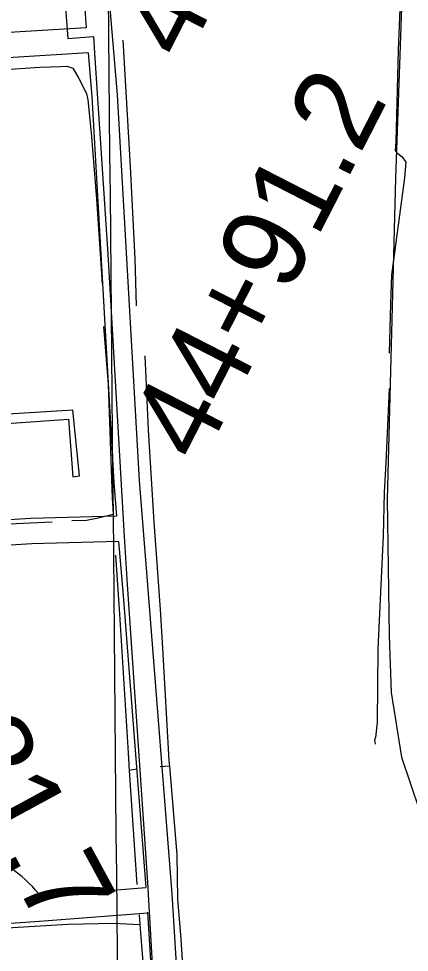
# Model space of a CAD drawing. Extents: x 3598634 to 3636690, y 517270 to 542944.
# Drawn here: x 3618480 to 3618943, y 532624 to 533730 of the extents above; entities that cross this region are included whole.
import ezdxf

# ---------------------------------------------------------------- set-up
doc = ezdxf.new("R2010")
doc.units = 0
for name, color, linetype in [('V-GRID-MAJR', 7, 'Continuous'), ('V-ROAD-CNTR', 7, 'Continuous'), ('V-SITE-OTLN', 7, 'Continuous'), ('V-SURV-IDEN', 7, 'Continuous'), ('V-TOPO-SHOR', 7, 'Continuous'), ('V-UTIL-LINE', 7, 'Continuous')]:
    doc.layers.add(name, color=color, linetype=linetype)

msp = doc.modelspace()

# ---------------------------------------------------------------- linework, layer by layer
at = {"layer": 'V-GRID-MAJR'}
msp.add_spline([(3618688.126, 522824.368), (3618631.739, 528881.623), (3618575.3200000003, 534942.3470000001), (3618518.901, 541003.085), (3618518.869, 541006.5380000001)], degree=3, dxfattribs=at)
at = {"layer": 'V-ROAD-CNTR'}
for points in [[(3619219.9145215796, 534324.0093257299), (3619206.102549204, 534275.35442304), (3619176.9376075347, 534236.3695010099), (3619115.1567310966, 534156.29966115), (3619042.2828768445, 534040.5618926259), (3619000.4559604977, 533979.1660154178), (3618969.343022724, 533912.5291486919), (3618942.837075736, 533846.1042815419), (3618935.526090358, 533799.4893747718), (3618926.589108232, 533541.027891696), (3618916.4771284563, 533160.012653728), (3618919.048123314, 532999.0249757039), (3618921.288118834, 532931.6421104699), (3618933.62509416, 532854.8872639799), (3618954.7500519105, 532791.593390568), (3618968.012025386, 532734.3305050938), (3618985.6189901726, 532604.676764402), (3619018.862923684, 532130.184713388), (3619043.9958734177, 531655.553662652), (3618810.58034025, 531632.7107083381), (3618782.5033964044, 531631.8167101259), (3618729.4055026, 531624.7497242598)], [(3618522.2249169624, 534279.1574154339), (3618527.482906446, 534211.0755515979), (3618558.558844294, 533735.331503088), (3618559.9198415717, 533719.114535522)], [(3618552.134857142, 534281.4674108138), (3618557.4068465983, 534213.207547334), (3618588.4767844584, 533737.5634986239), (3618596.699768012, 533639.6066945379), (3618622.53571634, 533182.582608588), (3618633.446694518, 533048.905875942), (3618661.3826386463, 532693.043587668), (3618688.0935852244, 532257.341459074), (3618714.078533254, 531845.438282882), (3618725.868509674, 531684.253605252), (3618729.4055026, 531624.7497242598)], [(3618559.92084157, 533719.114535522), (3618312.0443373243, 533703.7455662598), (3618179.040603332, 533693.0975875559), (3618051.9228575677, 533682.7066083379), (3617937.045087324, 533677.777618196), (3617826.615308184, 533673.2776271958)], [(3618562.429836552, 533689.212595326), (3618314.170333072, 533673.819626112), (3618274.4384125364, 533670.638632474)], [(3618562.429836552, 533689.212595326), (3618566.7698278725, 533637.504698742), (3618592.6037762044, 533180.5146127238), (3618595.884769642, 533140.323693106)], [(3618595.88576964, 533140.3226931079), (3618494.1659730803, 533137.730698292), (3618310.5403403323, 533126.1567214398)], [(3618598.3297647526, 533110.3757530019), (3618495.4919704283, 533107.7547582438), (3618216.7555279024, 533090.1857933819), (3617956.3310487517, 533072.857828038), (3617866.8522277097, 533067.4688388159)], [(3618598.3297647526, 533110.3757530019), (3618603.542754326, 533046.5118807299), (3618630.7026227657, 532700.5320160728)], [(3618505.311465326, 532690.7503942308), (3618503.6532838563, 532692.9208551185), (3618499.962415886, 532697.3708852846), (3618496.097971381, 532701.6652087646), (3618492.0672013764, 532705.7986735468), (3618487.876376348, 532709.7649900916), (3618483.530859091, 532713.5565683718), (3618479.042725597, 532717.1671712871), (3618474.413681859, 532720.5945192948), (3618469.648790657, 532723.8299944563), (3618464.7632414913, 532726.8678038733), (3618459.758905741, 532729.7016921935), (3618455.1065853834, 532732.0935861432), (3618403.7617469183, 532760.2884909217)], [(3618504.912696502, 532690.7233632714), (3618517.7836619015, 532691.5958350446), (3618630.597150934, 532700.5447059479)], [(3617899.9676740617, 532619.0491477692), (3617937.988811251, 532621.8086414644), (3618108.2972284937, 532634.260796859), (3618324.74355688, 532648.441197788), (3618499.0534782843, 532660.2573448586), (3618519.9843380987, 532661.6761649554), (3618632.969433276, 532670.638648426)], [(3618632.6635868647, 532671.2325881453), (3618658.151645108, 532255.4794627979), (3618684.146593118, 531843.400286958), (3618695.934569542, 531682.2696092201), (3618699.762561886, 531617.8667380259)]]:
    msp.add_lwpolyline(points, dxfattribs=at)
at = {"layer": 'V-SITE-OTLN'}
for points in [[(3616721.157, 533632.576), (3616899.8000000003, 533698.205), (3616988.87, 533732.75), (3616986.457, 533784.804), (3616974.0470000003, 533889.904), (3617157.898, 533936.707), (3617509.6210000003, 534027.0210000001), (3617753.552, 534092.697), (3617870.505, 534121.672), (3617874.2, 534100.176), (3618103.256, 534130.888), (3618391.041, 534154.427), (3618505.486, 534161.542), (3618526.472, 533864.2710000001), (3618538.198, 533706.292), (3618568.566, 533708.84), (3618569.869, 533688.905)], [(3618569.869, 533688.905), (3618585.413, 533450.954), (3618605.043, 533116.261), (3618608.375, 533059.431), (3618632.648, 532706.325), (3618633.8170000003, 532685.753), (3618649.886, 532403.064), (3618673.0160000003, 532133.854), (3618695.2120000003, 531790.738), (3618697.414, 531756.6900000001), (3618708.594, 531603.602), (3618727.133, 531349.7), (3618745.423, 530987.283), (3618752.7800000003, 530856.316)]]:
    msp.add_lwpolyline(points, dxfattribs=at)
at = {"layer": 'V-TOPO-SHOR'}
for p, q in [((3618658.522, 532844.395), (3618647.474, 532843.595)), ((3618620.501, 532840.867), (3618610.923, 532839.316))]:
    msp.add_line(p, q, dxfattribs=at)
for points in [[(3618933.921, 533799.921), (3618929.661, 533692.4130000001), (3618926.686, 533584.178), (3618926.137, 533573.633), (3618927.978, 533570.893), (3618934.329, 533565.937), (3618938.636, 533559.764), (3618937.018, 533541.3420000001), (3618921.799, 533426.474), (3618920.681, 533392.164), (3618918.952, 533333.431)], [(3618603.149, 533704.373), (3618611.892, 533554.554), (3618617.45, 533445.213), (3618619.1890000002, 533389.608)], [(3618418.693, 533665.045), (3618451.924, 533668.607), (3618504.998, 533672.459), (3618529.488, 533673.172), (3618537.432, 533673.42), (3618543.92, 533671.099), (3618551.215, 533658.824), (3618560.2120000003, 533641.174), (3618561.8140000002, 533633.8200000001), (3618565.7260000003, 533594.623), (3618572.234, 533516.297), (3618578.896, 533415.493)], [(3618580.25, 533365.194), (3618585.952, 533296.823), (3618590.8340000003, 533161.743), (3618592.075, 533142.76), (3618592.309, 533139.1950000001)], [(3618629.326, 533330.259), (3618633.377, 533242.807), (3618640.252, 533133.399), (3618643.302, 533090.282), (3618647.4390000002, 533029.926), (3618650.349, 532984.169), (3618657.972, 532850.931), (3618658.522, 532844.395), (3618667.38, 532739.409), (3618667.974, 532687.166), (3618672.1010000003, 532639.366), (3618677.573, 532553.823), (3618689.8510000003, 532408.446), (3618693.859, 532332.893), (3618695.092, 532305.733), (3618698.551, 532270.523), (3618703.8510000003, 532232.576), (3618705.221, 532208.051)], [(3618918.772, 533291.804), (3618914.846, 533203.4450000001), (3618913.032, 533168.512), (3618911.682, 533117.029), (3618905.392, 532983.191), (3618904.829, 532895.981), (3618902.5870000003, 532878.251), (3618901.757, 532874.991), (3618902.1750000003, 532870.3420000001)], [(3618311.4420000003, 533182.408), (3618316.592, 533149.115), (3618320.068, 533136.551), (3618325.8510000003, 533128.682), (3618335.2090000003, 533123.38), (3618349.688, 533124.005), (3618433.935, 533129.95), (3618519.447, 533133.7660000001)], [(3618542.919, 533135.3), (3618560.143, 533135.781), (3618574.045, 533138.4990000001), (3618592.075, 533142.76)], [(3618594.594, 533094.135), (3618599.569, 533024.48), (3618609.536, 532860.057), (3618610.923, 532839.316), (3618619.95, 532704.2)], [(3618622.715, 532668.368), (3618623.649, 532656.602), (3618629.506, 532582.757), (3618634.661, 532503.84)], [(3618433.077, 532650.716), (3618537.975, 532656.965), (3618592.397, 532658.267), (3618623.649, 532656.602)]]:
    msp.add_lwpolyline(points, dxfattribs=at)
at = {"layer": 'V-UTIL-LINE'}
msp.add_lwpolyline([(3618350.335, 533238.41), (3618415.828, 533242.568), (3618415.357, 533246.715), (3618538.807, 533255.4230000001), (3618544.193, 533187.116), (3618551.801, 533188.095), (3618544.1720000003, 533266.136), (3618128.492, 533240.309), (3618114.592, 533462.287), (3618086.389, 533461.691), (3618090.057, 533426.456), (3618085.1890000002, 533425.335), (3618086.926, 533419.06), (3617993.842, 533412.9), (3617994.501, 533399.123), (3618097.035, 533402.0430000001), (3618122.987, 533015.215), (3617754.838, 532991.731), (3617757.269, 532972.365), (3618140.708, 532999.179)], dxfattribs=at)

# ---------------------------------------------------------------- texts
at = {"layer": 'V-SURV-IDEN'}
for s, height, rotation, p in [('42+89.0', 100, 62.86579687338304, (3618677.1917360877, 533677.1231863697)), ('44+91.2', 99.99999999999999, 62.89010859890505, (3618696.065405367, 533200.4460854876)), ('30+81.7', 100.00000000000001, 298.47678765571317, (3618277.6434428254, 533070.5640038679))]:
    msp.add_text(s, height=height, rotation=rotation, dxfattribs=at).set_placement(p)

doc.saveas('drawing.dxf')
